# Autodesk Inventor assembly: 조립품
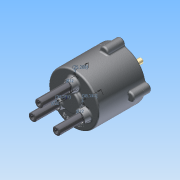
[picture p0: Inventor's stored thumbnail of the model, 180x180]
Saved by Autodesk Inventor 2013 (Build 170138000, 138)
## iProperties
Created: 2014-12
Part Number: 조립품
Document SubType Name: Assembly
Designer: Administrator
Author: Administrator
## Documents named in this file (14)
- C:\Users\CANON\Desktop\Inventor1급-강정희\조립품.iam
- C:\Users\CANON\Desktop\Inventor1급-강정희\몸체.ipt
- C:\Users\CANON\Desktop\Inventor1급-강정희\판캠.ipt
- C:\Users\CANON\Desktop\Inventor1급-강정희\베어링 NA 4900.ipt
- C:\Users\CANON\Desktop\Inventor1급-강정희\메인 축.ipt
- C:\Users\CANON\Desktop\Inventor1급-강정희\멈춤링 10 x 1.ipt
- C:\Users\CANON\Desktop\Inventor1급-강정희\멈춤링 22 x 1.2.ipt
- C:\Users\CANON\Desktop\Inventor1급-강정희\슬라이드 축.ipt
- C:\Users\CANON\Desktop\Inventor1급-강정희\커버.ipt
- C:\Users\CANON\Desktop\Inventor1급-강정희\오일실.ipt
- C:\Users\CANON\Desktop\Inventor1급-강정희\M5x0.5x20.ipt
- C:\Users\CANON\Desktop\Inventor1급-강정희\가변스프링 1.ipt
- C:\Users\CANON\Desktop\Inventor1급-강정희\가변스프링2.ipt
- C:\Users\CANON\Desktop\Inventor1급-강정희\가변스프링3.ipt
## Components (7 placed, 4 different names)
1. 가변스프링 1:1 — Mate:15, Mate:22, Mate:25
2. 가변스프링2:1 — Mate:16, Mate:23, Mate:27
3. 가변스프링3:1 — Mate:17, Mate:21, Mate:26
4. M5x0.5x20:1 — Insert:7
5. M5x0.5x20:2
6. M5x0.5x20:3
7. M5x0.5x20:4
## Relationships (10: Mate 9, Insert 1)
- Insert:7: M5x0.5x20:1
- Mate:15: 가변스프링 1:1
- Mate:16: 가변스프링2:1
- Mate:17: 가변스프링3:1
- Mate:21: 가변스프링3:1
- Mate:22: 가변스프링 1:1
- Mate:23: 가변스프링2:1
- Mate:25: 가변스프링 1:1
- Mate:26: 가변스프링3:1
- Mate:27: 가변스프링2:1
